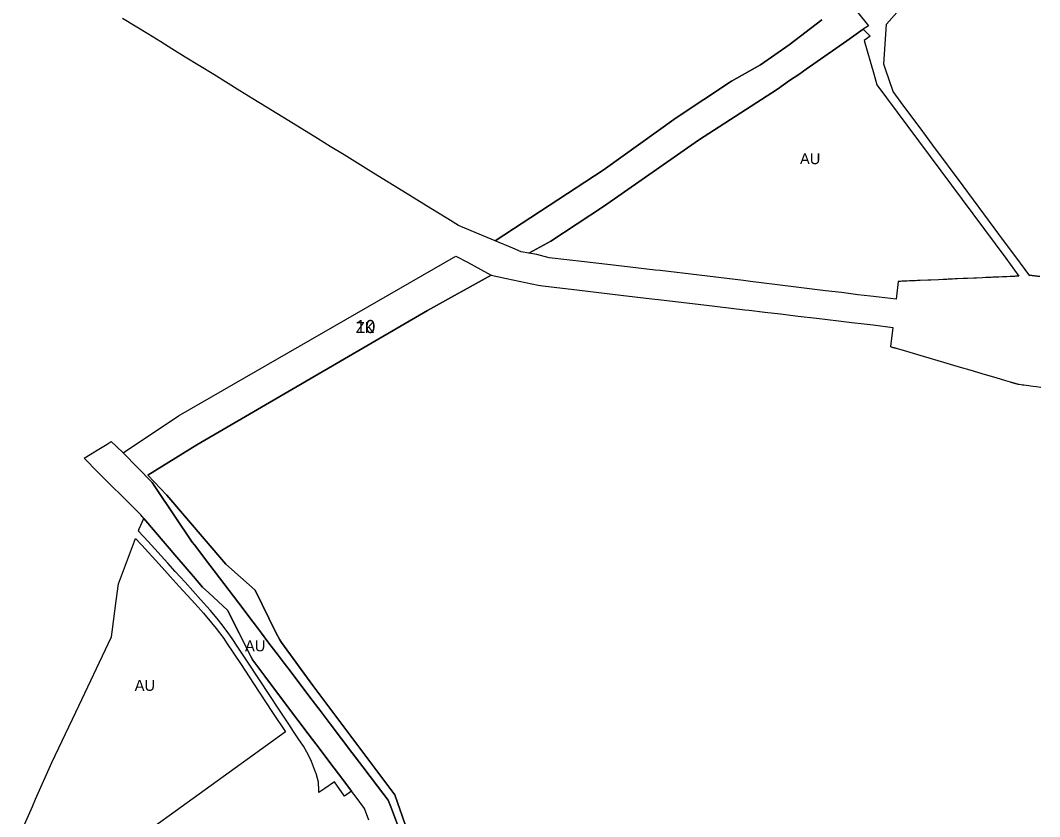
# Model space of a CAD drawing. Extents: x -537068 to -534056, y -1176840 to -1172401.
# Drawn here: x -537006.7 to -536540.8, y -1174581.9 to -1174218 of the extents above; entities that cross this region are included whole.
import ezdxf

# ---------------------------------------------------------------- set-up
doc = ezdxf.new("R2010")
doc.units = 0
for name, color, linetype in [('90640013', 7, 'Continuous'), ('90710023', 7, 'Continuous'), ('90750013', 7, 'Continuous'), ('ID_navrh', 7, 'Continuous')]:
    doc.layers.add(name, color=color, linetype=linetype)

msp = doc.modelspace()

# ---------------------------------------------------------------- linework, layer by layer
at = {"layer": '90640013'}
msp.add_lwpolyline([(-536847.43, -1174583.64), (-536849.37, -1174578.18), (-536853.23, -1174573.07), (-536855.32, -1174570.31), (-536859.83, -1174564.33), (-536864.8, -1174557.75), (-536869.7, -1174551.26), (-536875.13, -1174544.08), (-536879.85, -1174537.82), (-536885.04, -1174530.94), (-536895.01, -1174517.74), (-536900.51, -1174510.45), (-536901.35, -1174508.78), (-536903.35, -1174504.8), (-536906.7, -1174498.12), (-536911.83, -1174487.9), (-536911.98, -1174487.6), (-536920.58, -1174479.74), (-536923.47, -1174477.09), (-536927.63, -1174472.21), (-536935.21, -1174463.33), (-536950.27, -1174445.69), (-536951.72, -1174443.99), (-536952.94, -1174442.78), (-536972.55, -1174423.31), (-536973.4, -1174422.41), (-536975.26, -1174420.44), (-536977.51, -1174418.05), (-536972.8, -1174415.19), (-536971.61, -1174414.48), (-536967.08, -1174411.73), (-536965.16, -1174410.56), (-536962.82, -1174412.8), (-536959.76, -1174415.72), (-536946.53, -1174429.18), (-536944.35, -1174432.42), (-536928.15, -1174456.44), (-536927.13, -1174457.78), (-536920.15, -1174466.99), (-536913.8, -1174475.36), (-536906.91, -1174484.44), (-536900.32, -1174493.11), (-536898.39, -1174495.66), (-536896.58, -1174498.04), (-536893.56, -1174502.02), (-536891.02, -1174505.37), (-536888.89, -1174508.18), (-536886.13, -1174511.82), (-536883.47, -1174515.33), (-536874.4, -1174527.28), (-536869.7, -1174533.48), (-536865.14, -1174539.49), (-536859.89, -1174546.41), (-536855.16, -1174552.64), (-536850.22, -1174559.15), (-536843.46, -1174568.06), (-536838.62, -1174574.44), (-536837.45, -1174577.47), (-536833.4, -1174588)], dxfattribs=at)
at = {"layer": '90710023'}
for points in [[(-536629.05, -1174207.9), (-536619.11, -1174220.46), (-536621.41, -1174222.06), (-536628.95, -1174227.33), (-536647.48, -1174240.27), (-536650.9, -1174242.7), (-536655.21, -1174245.53), (-536660.63, -1174249.48), (-536696.77, -1174272.73), (-536740.11, -1174303.11), (-536764.27, -1174318.86), (-536774.32, -1174324.36), (-536777.86, -1174323.74), (-536781.56, -1174322.19), (-536789.62, -1174318.82), (-536740.36, -1174286.49), (-536706.97, -1174262.51), (-536681.6, -1174245.85), (-536668.42, -1174238.35), (-536655.27, -1174229.14), (-536640.42, -1174217.81)], [(-536833.4, -1174588), (-536837.45, -1174577.47), (-536838.62, -1174574.44), (-536843.46, -1174568.06), (-536850.22, -1174559.15), (-536855.16, -1174552.64), (-536859.89, -1174546.41), (-536865.14, -1174539.49), (-536869.7, -1174533.48), (-536874.4, -1174527.28), (-536883.47, -1174515.33), (-536886.13, -1174511.82), (-536888.89, -1174508.18), (-536891.02, -1174505.37), (-536893.56, -1174502.02), (-536896.58, -1174498.04), (-536898.39, -1174495.66), (-536900.32, -1174493.11), (-536906.91, -1174484.44), (-536913.8, -1174475.36), (-536920.15, -1174466.99), (-536927.13, -1174457.78), (-536928.15, -1174456.44), (-536944.35, -1174432.42), (-536946.53, -1174429.18), (-536959.76, -1174415.72), (-536934.44, -1174398.77), (-536807.66, -1174325.78), (-536802.4, -1174328.6), (-536796.2, -1174331.92), (-536791.46, -1174334.47), (-536820.61, -1174350.66), (-536926.13, -1174412.06), (-536948.53, -1174425.88), (-536939.8, -1174435.07), (-536912.85, -1174466.49), (-536899.48, -1174478.39), (-536890.01, -1174497.84), (-536888.12, -1174501.1), (-536887.36, -1174502.41), (-536873.06, -1174521.97), (-536872.53, -1174522.68), (-536835.56, -1174572.01), (-536816.72, -1174626.2)]]:
    msp.add_lwpolyline(points, dxfattribs=at)
at = {"layer": '90750013'}
for points in [[(-536540.75, -1174335.15), (-536541.06, -1174335.11), (-536541.36, -1174335.07), (-536541.66, -1174335.03), (-536541.96, -1174334.99), (-536542.27, -1174334.95), (-536542.57, -1174334.92), (-536542.87, -1174334.88), (-536543.17, -1174334.84), (-536543.47, -1174334.8), (-536543.78, -1174334.76), (-536544.08, -1174334.72), (-536544.38, -1174334.68), (-536544.42, -1174334.68), (-536544.43, -1174334.68), (-536544.44, -1174334.68), (-536544.45, -1174334.67), (-536544.46, -1174334.67), (-536544.47, -1174334.67), (-536544.48, -1174334.67), (-536544.49, -1174334.67), (-536544.5, -1174334.67), (-536544.51, -1174334.67), (-536544.52, -1174334.67), (-536544.53, -1174334.67), (-536544.54, -1174334.67), (-536544.55, -1174334.67), (-536544.58, -1174334.67), (-536544.59, -1174334.67), (-536544.6, -1174334.67), (-536544.61, -1174334.67), (-536544.63, -1174334.67), (-536544.64, -1174334.67), (-536544.65, -1174334.67), (-536544.66, -1174334.67), (-536544.66, -1174334.68), (-536544.67, -1174334.68), (-536544.68, -1174334.68), (-536544.69, -1174334.68), (-536544.7, -1174334.68), (-536544.71, -1174334.68), (-536544.72, -1174334.68), (-536544.73, -1174334.68), (-536544.78, -1174334.68), (-536544.83, -1174334.68), (-536544.89, -1174334.69), (-536544.97, -1174334.69), (-536545.07, -1174334.69), (-536545.23, -1174334.7), (-536545.34, -1174334.71), (-536551.71, -1174326.12), (-536556.82, -1174319.23), (-536575.77, -1174293.69), (-536589.61, -1174275.03), (-536595.45, -1174267.15), (-536602.81, -1174257.23), (-536607.74, -1174250.59), (-536611.2, -1174240.36), (-536611.97, -1174238.08), (-536610.87, -1174219.78), (-536567.42, -1174170.5)], [(-536640.42, -1174217.81), (-536655.27, -1174229.14), (-536668.42, -1174238.35), (-536681.6, -1174245.85), (-536706.97, -1174262.51), (-536740.36, -1174286.49), (-536789.62, -1174318.82), (-536797, -1174315.73), (-536805.43, -1174312.2), (-536806.4, -1174311.79), (-536811.3, -1174308.77), (-536819.05, -1174303.99), (-536831.83, -1174296.12), (-536845.36, -1174287.78), (-536858.72, -1174279.55), (-536865.05, -1174275.65), (-536870.88, -1174272.06), (-536882.04, -1174265.17), (-536894.16, -1174257.7), (-536900.45, -1174253.83), (-536906.38, -1174250.17), (-536918.31, -1174242.82), (-536931.34, -1174234.79), (-536937.48, -1174231), (-536942.59, -1174227.85), (-536948.51, -1174224.2), (-536954.3, -1174220.63), (-536960.1, -1174217.1)], [(-536816.72, -1174626.2), (-536835.56, -1174572.01), (-536872.53, -1174522.68), (-536873.06, -1174521.97), (-536887.36, -1174502.41), (-536888.12, -1174501.1), (-536890.01, -1174497.84), (-536899.48, -1174478.39), (-536912.85, -1174466.49), (-536939.8, -1174435.07), (-536948.53, -1174425.88), (-536926.13, -1174412.06), (-536820.61, -1174350.66), (-536791.46, -1174334.47), (-536784.5, -1174335.95), (-536769.99, -1174339.03), (-536767.9, -1174339.28), (-536751.14, -1174341.3), (-536732.32, -1174343.57), (-536718.13, -1174345.28), (-536713.8, -1174345.79), (-536694.33, -1174348.06), (-536675.53, -1174350.26), (-536673.61, -1174350.49), (-536666.43, -1174351.34), (-536659.2, -1174352.2), (-536651.22, -1174353.15), (-536642.85, -1174354.14), (-536632.68, -1174355.35), (-536626.59, -1174356.07), (-536620.97, -1174356.74), (-536616.91, -1174357.25), (-536607.93, -1174358.38), (-536608.98, -1174367.14), (-536608.97, -1174367.14), (-536608.95, -1174367.15), (-536608.94, -1174367.15), (-536608.9, -1174367.16), (-536608.87, -1174367.17), (-536608.84, -1174367.18), (-536608.8, -1174367.19), (-536608.79, -1174367.2), (-536608.77, -1174367.2), (-536608.75, -1174367.21), (-536608.72, -1174367.22), (-536608.67, -1174367.23), (-536608.57, -1174367.26), (-536608.28, -1174367.35), (-536607.91, -1174367.46), (-536607.79, -1174367.49), (-536607.41, -1174367.61), (-536607.13, -1174367.69), (-536606.91, -1174367.75), (-536606.6, -1174367.84), (-536606.38, -1174367.91), (-536605.96, -1174368.03), (-536603.24, -1174368.81), (-536600.21, -1174369.7), (-536594, -1174371.48), (-536584.69, -1174374.31), (-536577.15, -1174376.5), (-536572.72, -1174377.81), (-536565.68, -1174379.89), (-536560.82, -1174381.31), (-536556.34, -1174382.65), (-536555.38, -1174382.92), (-536554.26, -1174383.25), (-536553.93, -1174383.35), (-536553.69, -1174383.42), (-536553.58, -1174383.45), (-536553.47, -1174383.48), (-536553.44, -1174383.49), (-536553.42, -1174383.5), (-536553.38, -1174383.51), (-536553.35, -1174383.52), (-536553.33, -1174383.52), (-536553.32, -1174383.53), (-536553.31, -1174383.53), (-536553.2, -1174383.56), (-536553.17, -1174383.57), (-536553.13, -1174383.58), (-536553.08, -1174383.6), (-536552.9, -1174383.65), (-536552.7, -1174383.71), (-536552.47, -1174383.78), (-536552.32, -1174383.82), (-536552.16, -1174383.87), (-536552.01, -1174383.91), (-536551.88, -1174383.95), (-536551.73, -1174384), (-536551.52, -1174384.05), (-536551.25, -1174384.14), (-536551.11, -1174384.18), (-536550.8, -1174384.27), (-536550.72, -1174384.28), (-536550.13, -1174384.35), (-536549.25, -1174384.47), (-536548.67, -1174384.54), (-536548.08, -1174384.62), (-536546.91, -1174384.77), (-536545.75, -1174384.92), (-536544.87, -1174385.04), (-536543.7, -1174385.19), (-536542.24, -1174385.39), (-536540.21, -1174385.66)], [(-537006.73, -1174589.74), (-537001.24, -1174577.3), (-536999.78, -1174573.98), (-536992.38, -1174557.2), (-536981.45, -1174534.21), (-536965.11, -1174499.82), (-536964.81, -1174497.53), (-536962.95, -1174483.34), (-536961.93, -1174475.6), (-536954.05, -1174454.82), (-536951.21, -1174457.91), (-536941.93, -1174468.07), (-536938.2, -1174472.15), (-536934.08, -1174476.7), (-536926.87, -1174484.67), (-536922.97, -1174488.98), (-536919.35, -1174493.41), (-536917.26, -1174495.97), (-536913.78, -1174500.58), (-536912.46, -1174502.53), (-536905.87, -1174512.49), (-536900.14, -1174521.16), (-536891.43, -1174534.31), (-536885.49, -1174543.27), (-536995.69, -1174622.76)]]:
    msp.add_lwpolyline(points, dxfattribs=at)
for points in [[(-536606.37, -1174345.41), (-536606.46, -1174345.4), (-536614.1, -1174344.54), (-536618.07, -1174344.1), (-536623.85, -1174343.39), (-536631.43, -1174342.46), (-536638.68, -1174341.57), (-536647.29, -1174340.51), (-536655.8, -1174339.46), (-536672.99, -1174337.33), (-536676.21, -1174336.95), (-536696.37, -1174334.54), (-536714.29, -1174332.4), (-536716.56, -1174332.13), (-536731.72, -1174330.37), (-536748.9, -1174328.37), (-536765.05, -1174326.5), (-536769.03, -1174325.44), (-536770.65, -1174325.01), (-536774.32, -1174324.36), (-536764.27, -1174318.86), (-536740.11, -1174303.11), (-536696.77, -1174272.73), (-536660.63, -1174249.48), (-536655.21, -1174245.53), (-536650.9, -1174242.7), (-536647.48, -1174240.27), (-536628.95, -1174227.33), (-536621.41, -1174222.06), (-536618.25, -1174225.18), (-536621.04, -1174227.22), (-536616.62, -1174242.52), (-536615.2, -1174247.42), (-536610.73, -1174253.44), (-536605.93, -1174259.9), (-536556.31, -1174326.75), (-536550.25, -1174334.92), (-536551.83, -1174334.99), (-536552.29, -1174335.01), (-536553.77, -1174335.08), (-536554.25, -1174335.1), (-536555.74, -1174335.17), (-536557.75, -1174335.25), (-536559.51, -1174335.33), (-536561.56, -1174335.42), (-536561.73, -1174335.43), (-536561.89, -1174335.44), (-536562.13, -1174335.45), (-536562.91, -1174335.48), (-536563.49, -1174335.51), (-536564.02, -1174335.53), (-536564.48, -1174335.55), (-536565.46, -1174335.59), (-536566.9, -1174335.65), (-536569.64, -1174335.78), (-536570.88, -1174335.83), (-536573.85, -1174335.96), (-536574.97, -1174336.01), (-536575.77, -1174336.05), (-536578.38, -1174336.16), (-536578.84, -1174336.18), (-536579.2, -1174336.2), (-536579.54, -1174336.21), (-536580.57, -1174336.26), (-536581.02, -1174336.28), (-536581.61, -1174336.3), (-536582.56, -1174336.34), (-536583.28, -1174336.38), (-536584.83, -1174336.45), (-536586.99, -1174336.54), (-536590.61, -1174336.7), (-536591.92, -1174336.76), (-536595.37, -1174336.92), (-536596.59, -1174336.97), (-536597.56, -1174337.01), (-536598.23, -1174337.04), (-536599.58, -1174337.1), (-536600.24, -1174337.12), (-536601.36, -1174337.17), (-536602.54, -1174337.23), (-536603.07, -1174337.25), (-536603.53, -1174337.27), (-536603.84, -1174337.28), (-536604.4, -1174337.31), (-536604.58, -1174337.32), (-536604.73, -1174337.32), (-536604.77, -1174337.33), (-536604.79, -1174337.33), (-536604.82, -1174337.33), (-536604.85, -1174337.33), (-536604.91, -1174337.33), (-536604.97, -1174337.33), (-536605.12, -1174337.34), (-536605.4, -1174337.35)], [(-536858.6, -1174572.62), (-536863.08, -1174566.08), (-536867.52, -1174569.06), (-536870.29, -1174570.93), (-536870.3, -1174570.06), (-536870.45, -1174566.17), (-536870.89, -1174564.58), (-536871.52, -1174562.3), (-536871.77, -1174561.68), (-536873.72, -1174556.72), (-536875, -1174553.88), (-536877.33, -1174549.77), (-536879.7, -1174546.18), (-536881.81, -1174543), (-536884.01, -1174539.67), (-536888.56, -1174532.8), (-536897.46, -1174519.36), (-536903.38, -1174510.45), (-536907.65, -1174504.01), (-536909.91, -1174500.61), (-536911.37, -1174498.46), (-536914.44, -1174494.34), (-536916.77, -1174491.47), (-536919.98, -1174487.52), (-536924.37, -1174482.66), (-536931.44, -1174474.85), (-536935.9, -1174469.92), (-536939.32, -1174466.18), (-536948.39, -1174456.27), (-536952.79, -1174451.48), (-536952.38, -1174450.41), (-536950.27, -1174445.69), (-536935.21, -1174463.33), (-536927.63, -1174472.21), (-536923.47, -1174477.09), (-536920.58, -1174479.74), (-536911.98, -1174487.6), (-536911.83, -1174487.9), (-536906.7, -1174498.12), (-536903.35, -1174504.8), (-536901.35, -1174508.78), (-536900.51, -1174510.45), (-536895.01, -1174517.74), (-536885.04, -1174530.94), (-536879.85, -1174537.82), (-536875.13, -1174544.08), (-536869.7, -1174551.26), (-536864.8, -1174557.75), (-536859.83, -1174564.33), (-536855.32, -1174570.31)]]:
    msp.add_lwpolyline(points, close=True, dxfattribs=at)

# ---------------------------------------------------------------- texts
at = {"layer": '90710023'}
msp.add_text('ZK', height=5, rotation=0, dxfattribs=at).set_placement((-536853.42, -1174360.94))
at = {"layer": '90750013'}
for rotation, p in [(360, (-536650.35, -1174283.74)), (360, (-536904.05, -1174506.41)), (0, (-536954.47, -1174524.47))]:
    msp.add_text('AU', height=5, rotation=rotation, dxfattribs=at).set_placement(p)
at = {"layer": 'ID_navrh'}
msp.add_text('10', height=6, rotation=0, dxfattribs=at).set_placement((-536853.42, -1174360.94))

doc.saveas('drawing.dxf')
